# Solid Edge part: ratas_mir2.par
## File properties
Author: Kalle
Template: Iso Part.par
Last saved by: Kalle
Revision: 2
Application: Solid Edge
Accuracy: 0,990
Username: Kalle
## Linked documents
ratas.par
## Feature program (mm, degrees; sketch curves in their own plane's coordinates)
part copy "CopiedPart_1"
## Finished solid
Body 1: solid body, 6 faces, 6 edges, 0 vertices.
  Faces by surface: cylinder 3, plane 3
  Edges by curve: circle 6
Bounding box of the edges (mm): 30.000 x 12.000 x 30.000, from (13.8781, 0, -41.601) to (43.8781, 12, -11.601).
Cylindrical faces by radius (mm): R4 x1, R10 x1, R15 x1
Planar faces by outward normal: +y 2, -y 1
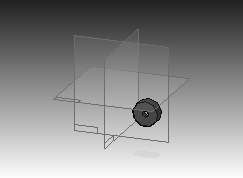
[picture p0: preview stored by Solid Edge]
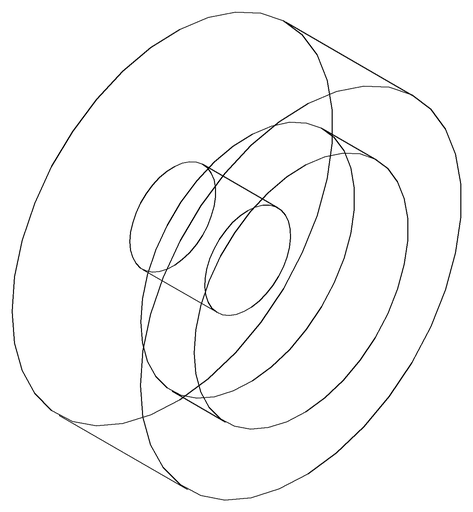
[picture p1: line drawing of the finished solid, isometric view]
